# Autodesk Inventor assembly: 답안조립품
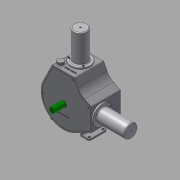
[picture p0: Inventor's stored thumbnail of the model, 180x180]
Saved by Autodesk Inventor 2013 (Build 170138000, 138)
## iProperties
Created: 2017-05
Part Number: 답안조립품
Document SubType Name: Assembly
Designer: dgall
Author: dgall
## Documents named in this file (13)
- C:\Users\dgall\Desktop\370507V1022\답안조립품.iam
- C:\Users\dgall\Desktop\370507V1022\본체.ipt
- C:\Users\dgall\Desktop\370507V1022\앞커버.ipt
- C:\Users\dgall\Desktop\370507V1022\축.ipt
- C:\Users\dgall\Desktop\370507V1022\베어링 20 x 37 x 9.ipt
- C:\Users\dgall\Desktop\370507V1022\커넥팅로드.ipt
- C:\Users\dgall\Desktop\370507V1022\커넥팅로드 캡.ipt
- C:\Users\dgall\Desktop\370507V1022\측정게이지.ipt
- C:\Users\dgall\Desktop\370507V1022\실린더.ipt
- C:\Users\dgall\Desktop\370507V1022\피스톤.ipt
- C:\Users\dgall\Desktop\370507V1022\피스톤 핀.ipt
- C:\Users\dgall\Desktop\370507V1022\볼트 M3 x 12.ipt
- C:\Users\dgall\Desktop\370507V1022\너트 M3.ipt
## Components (4 placed, 2 different names)
1. 피스톤:1
2. 피스톤:2
3. 피스톤 핀:1
4. 피스톤 핀:2
